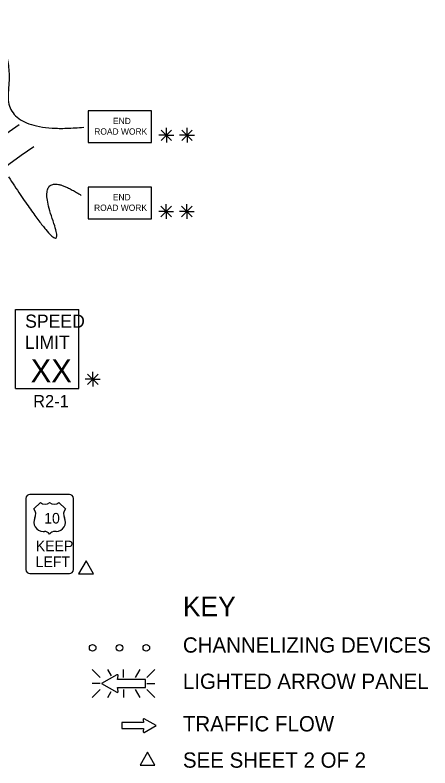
# Model space of a CAD drawing. Extents: x 16729 to 18464, y 5737 to 6974.
# Drawn here: x 17147.3 to 17399.4, y 6441.5 to 6898.8 of the extents above; entities that cross this region are included whole.
import ezdxf

# ---------------------------------------------------------------- set-up
doc = ezdxf.new("R2010")
doc.units = 0
for name, color, linetype in [('MT_SCRATCH_LEVEL_E', 7, 'Continuous'), ('PAVT_EDGE_EX', 7, 'Continuous'), ('TRAFFIC_SIGNS_PR', 7, 'Continuous'), ('TYPICAL_EX', 7, 'Continuous'), ('TYPICAL_TEXT_DIMEN_EX', 7, 'Continuous'), ('TYPICAL_TEXT_DIMEN_PR', 7, 'Continuous')]:
    doc.layers.add(name, color=color, linetype=linetype)

msp = doc.modelspace()

# ---------------------------------------------------------------- linework, layer by layer
at = {"layer": 'MT_SCRATCH_LEVEL_E'}
for p, q in [((17225.44, 6469.07), (17212.19, 6469.07)), ((17212.19, 6469.07), (17212.19, 6465.33)), ((17225.13, 6470.85), (17225.44, 6469.07)), ((17233.05, 6467.22), (17225.81, 6471.33)), ((17225.81, 6463.07), (17233.05, 6467.22)), ((17212.19, 6465.33), (17225.44, 6465.33)), ((17225.44, 6465.33), (17225.13, 6463.55))]:
    msp.add_line(p, q, dxfattribs=at)
for centre, start, end in [((17225.59, 6470.93), 60.4248, 189.9638), ((17225.59, 6463.48), 170.0362, 299.7731)]:
    msp.add_arc(centre, 0.463, start, end, dxfattribs=at)
at = {"layer": 'PAVT_EDGE_EX'}
for radius in [316, 300]:
    msp.add_arc((17325.51, 6569.52), radius, 123.7854, 180, dxfattribs=at)
at = {"layer": 'TRAFFIC_SIGNS_PR'}
for p, q in [((17147.68, 6719.98), (17186.08, 6719.98)), ((17147.68, 6671.98), (17147.68, 6719.98)), ((17186.08, 6671.98), (17186.08, 6719.98)), ((17147.68, 6671.98), (17186.08, 6671.98)), ((17153.94, 6605.16), (17153.94, 6561.91)), ((17180.37, 6607.57), (17156.34, 6607.57)), ((17182.77, 6561.91), (17182.77, 6605.16)), ((17156.34, 6559.51), (17180.37, 6559.51)), ((17194.12, 6501.23), (17199.05, 6496.3)), ((17205.88, 6497.41), (17203.67, 6501.23)), ((17213.2, 6496.3), (17213.2, 6501.23)), ((17220.44, 6496.3), (17223.28, 6501.23)), ((17227.35, 6496.3), (17232.28, 6501.23)), ((17199.05, 6492.74), (17194.12, 6492.74)), ((17227.35, 6492.74), (17232.28, 6492.74)), ((17194.12, 6484.25), (17199.05, 6489.19)), ((17203.63, 6484.25), (17205.74, 6487.91)), ((17213.2, 6489.19), (17213.2, 6484.25)), ((17223.33, 6484.25), (17220.48, 6489.19)), ((17227.35, 6489.19), (17232.28, 6484.25))]:
    msp.add_line(p, q, dxfattribs=at)
for points in [[(17191.84, 6821.42), (17230.24, 6821.42), (17230.24, 6840.62), (17191.84, 6840.62)], [(17191.72, 6775.12), (17230.12, 6775.12), (17230.12, 6794.32), (17191.72, 6794.32)]]:
    msp.add_lwpolyline(points, close=True, dxfattribs=at)
for points in [[(17209.13, 6498.02), (17199.84, 6492.74), (17209.13, 6487.42)], [(17210, 6488.05), (17209.6, 6490.32), (17226.62, 6490.32), (17226.62, 6495.12), (17209.6, 6495.12), (17210.01, 6497.4)]]:
    msp.add_lwpolyline(points, dxfattribs=at)
for centre in [(17194.46, 6514.43), (17210.76, 6514.43), (17227.06, 6514.43)]:
    msp.add_circle(centre, 2, dxfattribs=at)
for centre, radius, start, end in [((17156.34, 6605.16), 2.4, 90, 180), ((17180.37, 6605.16), 2.4, 0, 90), ((17156.34, 6561.91), 2.4, 180, 270), ((17180.37, 6561.91), 2.4, 270, 0), ((17209.42, 6497.49), 0.598, 350.7308, 118.8916), ((17209.41, 6487.94), 0.597, 241.4833, 9.9593)]:
    msp.add_arc(centre, radius, start, end, dxfattribs=at)
at = {"layer": 'TYPICAL_EX'}
for p, q in [((17158.74, 6598.76), (17162.75, 6602.76)), ((17177.97, 6598.76), (17173.96, 6602.76)), ((17164.34, 6585.13), (17165.14, 6585.13)), ((17172.36, 6585.13), (17171.56, 6585.13))]:
    msp.add_line(p, q, dxfattribs=at)
for centre, radius, start, end in [((17165.55, 6605.68), 4.05, 226.1404, 313.8596), ((17171.16, 6605.68), 4.05, 226.1404, 313.8596), ((17154.95, 6595.55), 4.97, 333.0977, 40.1936), ((17181.76, 6595.55), 4.97, 139.8064, 206.9023), ((17164.35, 6590.73), 5.6, 152.6698, 269.9013), ((17172.35, 6590.73), 5.6, 270.0987, 27.3302), ((17165.15, 6581.11), 4.01, 37.1038, 90.1385), ((17171.55, 6581.11), 4.01, 89.8615, 142.8962)]:
    msp.add_arc(centre, radius, start, end, dxfattribs=at)
at = {"layer": 'TYPICAL_TEXT_DIMEN_PR'}
for p, q in [((17236.07, 6828.98), (17242.45, 6822.61)), ((17242.45, 6828.98), (17236.07, 6822.61)), ((17239.26, 6825.8), (17239.26, 6830.25)), ((17248.63, 6828.98), (17255, 6822.61)), ((17255, 6828.98), (17248.63, 6822.61)), ((17251.81, 6825.8), (17251.81, 6830.25)), ((17239.26, 6825.8), (17234.73, 6825.8)), ((17239.26, 6825.8), (17242.45, 6825.8)), ((17239.26, 6825.8), (17243.74, 6825.8)), ((17239.26, 6825.8), (17239.26, 6821.3)), ((17251.81, 6825.8), (17247.28, 6825.8)), ((17251.81, 6825.8), (17255, 6825.8)), ((17251.81, 6825.8), (17256.29, 6825.8)), ((17251.81, 6825.8), (17251.81, 6821.3)), ((17235.96, 6782.68), (17242.33, 6776.3)), ((17242.33, 6782.68), (17235.96, 6776.3)), ((17239.15, 6779.49), (17239.15, 6783.94)), ((17254.89, 6782.68), (17248.51, 6776.3)), ((17248.52, 6782.68), (17254.89, 6776.3)), ((17251.7, 6779.49), (17251.7, 6783.94)), ((17239.15, 6779.49), (17234.62, 6779.49)), ((17239.15, 6779.49), (17242.33, 6779.49)), ((17239.15, 6779.49), (17243.62, 6779.49)), ((17239.15, 6779.49), (17239.15, 6774.99)), ((17251.7, 6779.49), (17247.17, 6779.49)), ((17251.7, 6779.49), (17254.89, 6779.49)), ((17251.7, 6779.49), (17256.18, 6779.49)), ((17251.7, 6779.49), (17251.7, 6774.99)), ((17194.54, 6677.57), (17194.54, 6682.03)), ((17194.54, 6677.57), (17190.01, 6677.57)), ((17191.35, 6680.76), (17197.72, 6674.38)), ((17197.72, 6680.76), (17191.35, 6674.38)), ((17194.54, 6677.57), (17197.72, 6677.57)), ((17194.54, 6677.57), (17199.01, 6677.57)), ((17194.54, 6677.57), (17194.54, 6673.07))]:
    msp.add_line(p, q, dxfattribs=at)
for points in [[(17190.44, 6567.27), (17185.92, 6559.44), (17194.97, 6559.44)], [(17227.76, 6451.05), (17223.24, 6443.21), (17232.29, 6443.21)]]:
    msp.add_lwpolyline(points, close=True, dxfattribs=at)
for points in [[(17085.32, 6872.4), (17068.93, 6903.88), (17120.14, 6891.56), (17146.08, 6878.56), (17140.29, 6826.13), (17189.09, 6830.66)], [(17143.35, 6800.53), (17181.58, 6742.35), (17158.37, 6808.06), (17187.53, 6789.29)]]:
    msp.add_open_spline(points, degree=2, dxfattribs=at)

# ---------------------------------------------------------------- texts
at = {"layer": 'TRAFFIC_SIGNS_PR'}
for s, height, p in [('END', 3.831, (17206.84, 6832.55)), ('ROAD WORK', 3.831, (17195.45, 6826.16)), ('END', 3.831, (17206.73, 6786.24)), ('ROAD WORK', 3.831, (17195.33, 6779.86)), ('SPEED', 8, (17153.45, 6708.85)), ('LIMIT', 8, (17153.28, 6696.05)), ('XX', 14.031, (17156.79, 6675.74)), ('R2-1', 7.44, (17158.36, 6660.54)), ('10', 6.408, (17165.01, 6589.94)), ('KEEP', 6.408, (17159.88, 6573.12)), ('LEFT', 6.408, (17159.79, 6563.51))]:
    msp.add_text(s, height=height, dxfattribs=at).set_placement(p)
at = {"layer": 'TYPICAL_TEXT_DIMEN_EX'}
for s, height, p in [('KEY', 12, (17249.3, 6533.54)), ('CHANNELIZING DEVICES', 9.3, (17249.3, 6511.49)), ('LIGHTED ARROW PANEL', 9.3, (17249.3, 6489.44)), ('TRAFFIC FLOW', 9.3, (17249.3, 6463.64)), ('SEE SHEET 2 OF 2', 9.3, (17249.3, 6441.59))]:
    msp.add_text(s, height=height, dxfattribs=at).set_placement(p)

doc.saveas('drawing.dxf')
